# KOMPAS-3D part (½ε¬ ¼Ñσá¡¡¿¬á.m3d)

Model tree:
1. Эскиз:1
2. Операция выдавливания:1
     Расстояние 1 = 0.5; Расстояние 2 = 1
3. Эскиз:6
4. Операция выдавливания:3
     Расстояние 1 = 1; Расстояние 2 = 1
5. Скругление:8
     Радиус = 0.3
6. Эскиз:10
7. Операция выдавливания:7
     Расстояние 1 = 0.5; Расстояние 2 = 1
8. Эскиз:11
9. Операция выдавливания:8
     Расстояние 1 = 2; Расстояние 2 = 1
10. Скругление:10
     Радиус = 2
11. Эскиз:12
12. Вырезать элемент выдавливания:5
     Расстояние 2 = 12.05; Расстояние 1 = 12.05
13. Скругление:12
     Радиус = 1
14. Скругление:13
     Радиус = 0.2
15. Скругление:14
     Радиус = 0.1
16. Эскиз:13
17. Вырезать элемент выдавливания:6
     Расстояние 2 = 2; Расстояние 1 = 2
18. Эскиз:14
19. Операция выдавливания:9
     Расстояние 1 = 1.7; Расстояние 2 = 1
20. Фаска:1
     Угол = 45; Длина 1 = 2; Длина 2 = 2
21. Эскиз:15
22. Операция выдавливания:10
     Расстояние 1 = 1.7
23. Эскиз:16
24. Операция выдавливания:11
     Расстояние 1 = 1
25. Скругление:15
     Радиус = 1

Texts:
  Сплав АЛ8  ГОСТ 1583-93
